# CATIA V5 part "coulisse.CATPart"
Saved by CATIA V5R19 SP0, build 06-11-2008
Part number: coulisse
Publications: "epaisseur_rainure", "largeur_coulisse", "epaisseur_coulisse"
Bounding box of the stored display mesh (mm): x -25 to 55, y -686.669 to -156.669, z -60 to 20
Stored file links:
  C:\Users\rcousturie\Desktop\EU_thinkMotion\iao\IAO_MMS_Groupe1\vduret\vduret\vduret\CATIA_disque\coulisse.CATPart
  C:\Users\rcousturie\Desktop\EU_thinkMotion\iao\IAO_MMS_Groupe1\vduret\vduret\vduret\CATIA_disque\vduret.CATProduct
  C:\Users\rcousturie\Desktop\EU_thinkMotion\iao\IAO_MMS_Groupe1\vduret\vduret\vduret\CATIA_disque\bati.CATPart
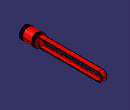
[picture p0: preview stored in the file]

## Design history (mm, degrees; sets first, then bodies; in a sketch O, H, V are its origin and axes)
Parameters
  diametre_cylindre = 70 mm
  largeur_coulisse = 60 mm
  largeur_rainure_coulisse = 30 mm
  longueur_cylindre = 100 mm
  epaisseur_coulisse = 30 mm
  epaisseur_rainure = 5 mm
External parameters (linked from other documents)
  External.longueur_bati = 700 mm
  External.diam_disque = 200 mm
  External.excentricite_maneton = 70 mm
  External.entraxe_bati = 350 mm
  External.diam_maneton = 20 mm
  External.diam_int_disque = 30 mm
  External.epaisseur_bati = 30 mm
  External.extrusion_disque = 25 mm
Body1 (main body)
  Sketch1 on yz-plane, origin (0, 0, 0), H (0, 1, 0), V (0, 0, 1)
    line L1 (-586.6692, 10) -> (-186.6692, 10)
    line L2 (-186.6692, -50) -> (-586.6692, -50)
    line L3 (-586.6692, -50) -> (-586.6692, 10)
    line L4 (-566.6692, -5) -> (-181.6692, -5)
    line L5 (-181.6692, -5) -> (-181.6692, -35)
    line L6 (-181.6692, -35) -> (-566.6692, -35)
    line L7 (-566.6692, -35) -> (-566.6692, -5)
    arc A1 centre (-186.6692, -20) radius 30 from (-186.6692, -50) to (-186.6692, 10) ccw
    length L1 = 400 {= External.entraxe_bati  +External.excentricite_maneton/2 +15mm}
    length L3 = 60 {= largeur_coulisse}
    length L4 = 385 {= External.entraxe_bati +External.excentricite_maneton /2}
    distance L4 L1 = 15 {= (largeur_coulisse -largeur_rainure_coulisse  )/2}
    length L7 = 30 {= largeur_rainure_coulisse}
    distance L7 L3 = 20
    horizontal: L1 H, L2 H, L4 H, L6 H
    vertical: L3 V, L5 V, L7 V
    tangency: A1 L2, L1 A1
  Pad1: profile Sketch1, direction (1, 0, 0), length 30 {= epaisseur_coulisse}
  Sketch2 on face of Pad1 from Sketch1.L3, origin (0, -586.6692, 0), H (1, 0, 0), V (0, 0, 1)
    circle A1 centre (15, -20) radius 40
    point P1 (15, -20)
    reference projected line E1 (65, 10) -> (95, 10) from edge [face of Pad1 from Sketch1.L3 | face of Pad1 from Sketch1.L1]
    reference projected line E2 (0, 10) -> (0, -60) from edge [start face of Pad1 | face of Pad1 from Sketch1.L3]
    radius A1 = 40 {= External.extrusion_disque +epaisseur_coulisse /2}
    distance P1 E1 = 30 {= largeur_coulisse /2}
    distance P1 E2 = 15 {= epaisseur_coulisse /2}
  Pad2: profile Sketch2, direction (0, -1, 0), length 100 {= longueur_cylindre}
  Plane1: type Offset, RefPlane start face of Pad1, Offset 20 {= (diametre_cylindre -epaisseur_coulisse )/2}, reversed
  Sketch3 on Plane1, origin (-20, 0, 0), H (0, 1, 0), V (0, 0, 1)
    circle A1 centre (-640, -20) radius 15
    point P1 (-640, -20)
    reference projected line E1 through (0, -20) direction (-1, 0) from axis of face of Pad2 from Sketch2.A1
    radius A1 = 15 {= External.diam_int_disque /2}
    coincidence: P1 E1
  Sketch4 on end face of Pad1, origin (30, 0, 0), H (0, 1, 0), V (0, 0, 1)
    arc A1 centre (-186.6692, -20) radius 25 from (-186.6692, -45) to (-186.6692, 5) ccw
    point P1 (-186.6692, -20)
    reference projected arc E1 centre (-186.6692, -20) radius 30 from (-186.6692, -50) to (-186.6692, 10) ccw from edge [face of Pad1 from Sketch1.A1 | end face of Pad1]
    line L1 (-186.6692, 5) -> (-576.6692, 5)
    line L2 (-186.6692, -45) -> (-576.6692, -45)
    line L3 (-576.6692, -45) -> (-576.6692, 5)
    radius A1 = 25 {= (largeur_coulisse -2*epaisseur_rainure )/2}
    length L1 = 390 {= External.entraxe_bati  +External.excentricite_maneton/2 +5mm}
    concentricity: P1 E1
    tangency: L1 A1, L2 A1
    vertical: L3 V
    horizontal: L1 H, L2 H
  Pocket1: profile Sketch4, direction (-1, 0, 0), length 25 {= epaisseur_coulisse -5mm}
  Pocket2: profile Sketch3, direction (1, 0, 0), length 25 {= External.extrusion_disque}
  Point1: type OnSurface, Support end face of Pad2, Length 0, Direction (0.9949, 0, -0.1005)
  Line1: type Normal, RefPoint Point1, RefSkin end face of Pad2, Start -20, End 20
  Plane2: type Offset, RefPlane Plane1, Offset 35 {= diametre_cylindre /2}
  Sketch5 on Plane2, origin (15, 0, 0), H (0, 1, 0), V (0, 0, 1)
    line L1 (-671.6692, 80) -> (-666.6692, 80)
    line L2 (-666.6692, 80) -> (-666.6692, 10)
    line L3 (-666.6692, 10) -> (-671.6692, 10)
    line L4 (-671.6692, 10) -> (-671.6692, 80)
    point P5 (-676.6692, 80)
    line L5 (-676.6692, 80) -> (-681.6692, 80)
    line L6 (-681.6692, 80) -> (-681.6692, 10)
    line L7 (-681.6692, 10) -> (-676.6692, 10)
    line L8 (-676.6692, 10) -> (-676.6692, 80)
    point P7 (-681.6692, 10)
    point P9 (-601.6692, 80)
    line L9 (-601.6692, 80) -> (-606.6692, 80)
    line L10 (-606.6692, 80) -> (-606.6692, 10)
    line L11 (-606.6692, 10) -> (-601.6692, 10)
    line L12 (-601.6692, 10) -> (-601.6692, 80)
    point P11 (-606.6692, 10)
    point P13 (-596.6692, 80)
    line L13 (-596.6692, 80) -> (-591.6692, 80)
    line L14 (-591.6692, 80) -> (-591.6692, 10)
    line L15 (-591.6692, 10) -> (-596.6692, 10)
    line L16 (-596.6692, 10) -> (-596.6692, 80)
    point P15 (-591.6692, 10)
    reference projected line E1 through (0, -20) direction (-1, 0) from axis of face of Pad2 from Sketch2.A1
    reference projected line E2 (-686.6692, -55) -> (-686.6692, 15) from edge [face of Pad2 from Sketch2.A1 | end face of Pad2]
    reference projected line E3 (-586.6692, 10) -> (-586.6692, -50) from edge [start face of Pad2 | end face of Pad1]
    length L14 = 70 {= diametre_cylindre}
    distance L15 E1 = 30 {= diametre_cylindre /2-5mm}
    distance L6 E2 = 5
    length L5 = 5
    distance L4 L8 = 5
    length L1 = 5
    distance L16 E3 = 10
    length L13 = 5
    length L9 = 5
    distance L12 L16 = 5
    horizontal: L1 H, L3 H, L5 H, L7 H, L9 H, L11 H, L13 H, L15 H
    vertical: L2 V, L4 V, L6 V, L8 V, L10 V, L12 V, L14 V, L16 V
    coincidence: P5 L1, P7 L3, P9 L1, P11 L3, P13 L1, P15 L3
  Groove1: profile Sketch5, axis Line1, angle 360
Relations
  Sketch1.length(L4) = =`Paramètres externes\entraxe_bati` (deactivated)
